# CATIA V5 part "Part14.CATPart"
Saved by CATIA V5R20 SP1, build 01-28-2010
Part number: doigt1
Publications: "Corps principal", "Longueur_griffe", "Hauteur_griffe"
Bounding box of the stored display mesh (mm): x -20 to -3, y -47.741 to 88.736, z 77.174 to 144.914
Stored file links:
  C:\Users\Fox\Desktop\IAO Projet\A RENDRE\Sauvegarde IFMA\Part14.CATPart
  C:\Users\Fox\Desktop\IAO Projet\A RENDRE\Sauvegarde IFMA\mpeyrard.CATProduct
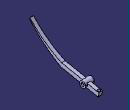
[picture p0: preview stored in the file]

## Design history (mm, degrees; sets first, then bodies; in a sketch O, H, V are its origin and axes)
Parameters
  Longueur_griffe = 70 mm
  Hauteur_griffe = 30 mm
Set1
  Plane1: linked copy from another document
  Line1 to Line3: linked copy from another document
Body1 (main body)
  Sketch1 on yz-plane, origin (0, 0, 0), H (0, 1, 0), V (0, 0, 1)
    circle A1 centre (60, 86.6025) radius 6
    point P1 (60, 86.6025)
    reference projected point E1 (60, 86.6025) from Line1
    reference projected point E2 (60, 86.6025) from Line1
    reference projected point E3 (60, 86.6025) from Line1
    circle A2 centre (60, 86.6025) radius 3
    radius A1 = 6
    distance E1 E2 = 0 (reference)
    distance E3 P1 = 0
    radius A2 = 3
  Pad1: profile Sketch1, direction (-1, 0, 0), length 20, opposite side length -3
  Sketch2 on Plane1, origin (0, 54.6358, 87.6583), H (-1, 0, 0), V (0, -0.9812, 0.1931)
    axis line L1 (13.5, -30.4671) -> (25.9822, -30.4671)
    reference projected line E1 (0, -5.4671) -> (0, -30.4671) from Line2
    reference projected point E2 (0, -30.4671) from Line3
    line L2 (6.5, -33.9671) -> (13.5, -33.9671)
    line L3 (13.5, -33.9671) -> (13.5, 41.0329)
    line L4 (13.5, 41.0329) -> (6.5, 41.0329)
    line L5 (6.5, 41.0329) -> (6.5, -33.9671)
    reference projected point E3 (0, -30.4671) from Line3
    distance L1 E2 = 0
    distance L5 E3 = 6.5
    length L2 = 7
    distance L2 L1 = 3.5
    length L3 = 75
    perpendicularity: L1 E1
    horizontal: L2 H, L4 H
    vertical: L3 V, L5 V
  Pad2: profile Sketch2, direction (0, 0.1931, 0.9812), length 4, mirrored extent
  Sketch3 on end face of Pad2, origin (-10.0769, 82.8794, 86.1761), H (1, 0, 0), V (0, 0.9812, -0.1931)
    point P1 (0.0769, 2.4689)
    reference projected point E1 (10.0769, 2.4689) from Line3
    reference projected line E2 (3.5769, 5.9689) -> (-3.4231, 5.9689) from edge [face of Pad2 from Sketch2.L2 | end face of Pad2]
    distance E1 P1 = 10
    distance P1 E2 = 3.5
  Hole1: placed by Sketch3, at (-10, 85.3019, 85.6993) direction (0, -0.1931, -0.9812), diameter 5, through (limit type 3)
  Sketch4 on face of Pad2 from Sketch2.L3, origin (-13.5, 0, 0), H (0, -1, 0), V (0, 0, 1)
    spline S1 through (-13.6029, 91.6579) (17.8415, 113.1347) (47.7409, 142.4608)
    reference projected point E1 (-13.6029, 91.6579) from vertex [face of Pad2 from Sketch2.L3 | start face of Pad2 | face of Pad2 from Sketch2.L4]
    line L1 (-13.6029, 91.6579) -> (-15.1478, 99.5073)
    point P1 (-13.6029, 91.6579)
    point P2 (-15.1478, 99.5073)
    reference projected point E2 (-15.1478, 99.5073) from vertex [face of Pad2 from Sketch2.L3 | end face of Pad2 | face of Pad2 from Sketch2.L4]
    spline S2 through (47.2581, 144.9138) (16.8759, 118.0405) (-15.1478, 99.5073)
    line L2 (47.7409, 142.4608) -> (47.2581, 144.9138)
    point P3 (47.7409, 142.4608)
    point P4 (47.2581, 144.9138)
    reference projected line E3 (-90.1568, 84.7437) -> (-16.5687, 99.2276) from edge [face of Pad2 from Sketch2.L3 | end face of Pad2]
    reference projected line E4 (-85.7702, 77.4536) -> (-12.182, 91.9375) from edge [start face of Pad2 | face of Pad2 from Sketch2.L3]
    point P5 (-13.6029, 91.6579)
    point P6 (47.2581, 144.9138)
    point P7 (47.7409, 142.4608)
    point P8 (-15.1478, 99.5073)
    point P9 (16.8759, 118.0405)
    point P10 (17.8415, 113.1347)
    length L2 = 2.5
    distance L1 L2 = 70 {= Longueur_griffe}
    distance P3 E3 = 30 {= Hauteur_griffe}
    distance P9 L1 = 35 {= Longueur_griffe/2}
    distance P10 L1 = 35 {= Longueur_griffe/2}
    distance P10 E4 = 15 {= Hauteur_griffe/2}
    distance P10 P9 = 5 {= 5mm}
    coincidence: E1 P5, P5 P1, P2 E2, P8 P2, P7 P3, P6 P4
  Pad3: profile Sketch4, direction (1, 0, 0), up to face of Pad2 from Sketch2.L5
  Sketch5 on face of Pad2 from Sketch2.L5, origin (-6.5, 58.98, 86.8879), H (0, 1, 0), V (0, 0, 1)
    point P1 (1.02, -0.2854)
    reference projected circle E1 centre (1.02, -0.2854) radius 3 from edge [face of Pad1 from Sketch1.A2 | face of Pad2 from Sketch2.L5]
    concentricity: E1 P1
  Hole2: placed by Sketch5, at (-6.5, 60, 86.6025) direction (-1, 0, 0), diameter 6, through (limit type 3)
